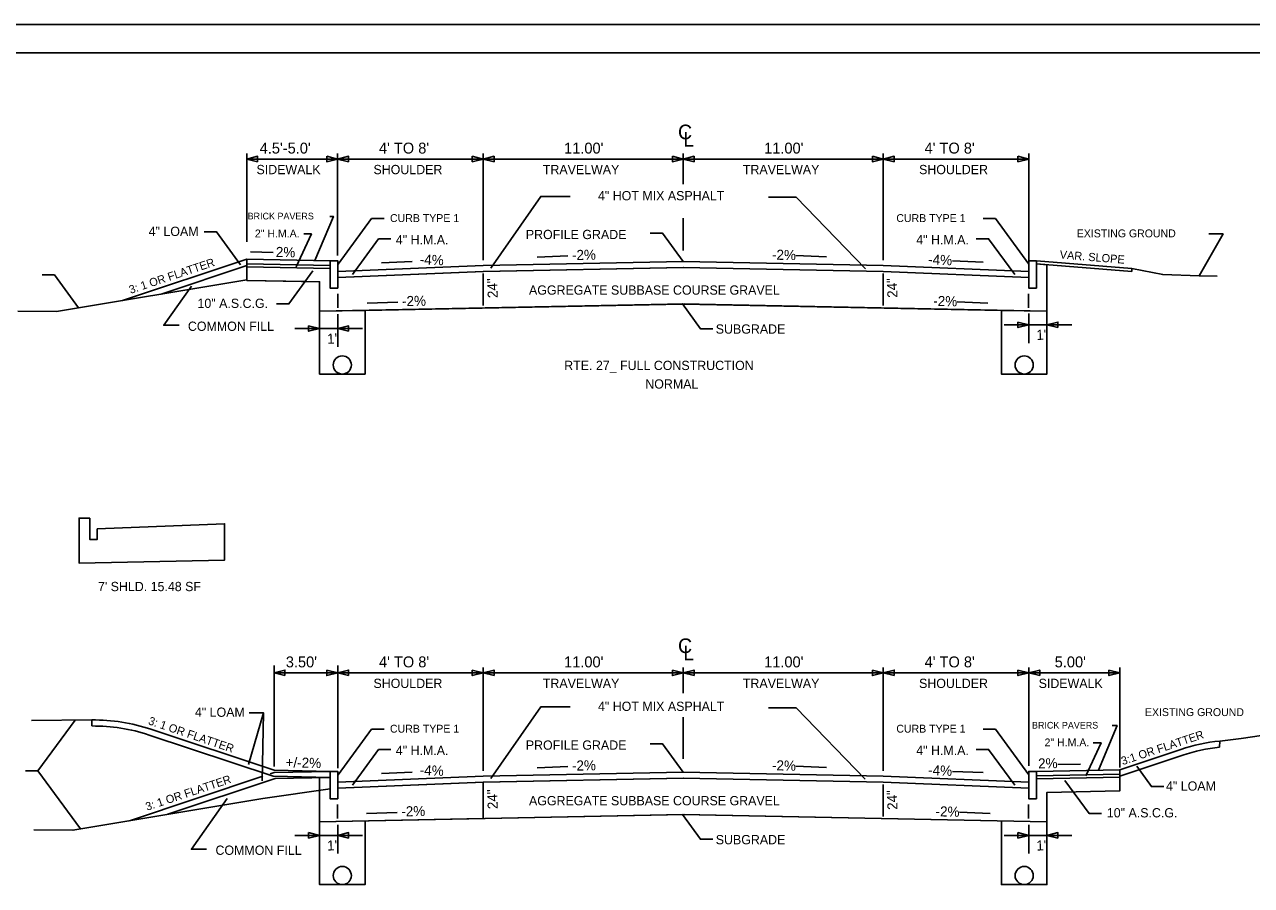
# Model space of a CAD drawing. Extents: x -60 to 130, y -2 to 86.
# Drawn here: x 7.9 to 75.3, y 38.2 to 85.6 of the extents above; entities that cross this region are included whole.
import ezdxf

# ---------------------------------------------------------------- set-up
doc = ezdxf.new("R2010")
doc.units = 0
for name, color, linetype in [('ANNOTATION', 7, 'Continuous'), ('BORDER', 7, 'Continuous'), ('D_Curb_Type1_Lt', 7, 'Continuous'), ('D_Curb_Type1_Rt', 7, 'Continuous'), ('D_Curb_Type_1_Rt', 7, 'Continuous'), ('D_Roadway_Edge_Shoulder', 7, 'Continuous'), ('D_Roadway_Edge_TW', 7, 'Continuous'), ('D_Roadway_FinishedGrade', 7, 'Continuous'), ('D_Roadway_Sidewalks_Paved', 7, 'Continuous'), ('D_Roadway_SubGrade', 7, 'Continuous'), ('DIMENSIONS', 7, 'Continuous'), ('junk gravel', 7, 'Continuous'), ('PATTERNING', 7, 'Continuous'), ('PDRAIN', 7, 'Continuous'), ('PLOT BOUNDARY', 7, 'Continuous'), ('S_Roadway_Centerline', 7, 'Continuous')]:
    doc.layers.add(name, color=color, linetype=linetype)

msp = doc.modelspace()

# ---------------------------------------------------------------- linework, layer by layer
at = {"layer": 'ANNOTATION'}
for p, q in [((21.541, 73.019), (20.296, 73.044)), ((29.184, 72.511), (27.501, 72.444)), ((37.74, 72.819), (36.056, 72.752)), ((50.284, 72.84), (51.968, 72.772)), ((58.908, 72.555), (60.592, 72.487)), ((28.396, 70.285), (26.713, 70.217)), ((59.153, 70.298), (60.836, 70.23)), ((37.74, 44.729), (36.056, 44.662)), ((50.284, 44.75), (51.968, 44.683)), ((64.696, 44.843), (65.941, 44.868)), ((29.184, 44.422), (27.501, 44.354)), ((58.908, 44.465), (60.592, 44.398)), ((28.354, 42.214), (26.67, 42.146)), ((59.28, 42.217), (60.963, 42.15))]:
    msp.add_line(p, q, dxfattribs=at)
for points in [[(37.873, 76.099), (36.254, 76.099), (33.509, 72.144)], [(48.778, 76.051), (50.301, 76.051), (54.117, 72.119)], [(24.652, 75.001), (24.858, 75.001), (23.836, 72.572)], [(27.639, 74.882), (26.959, 74.882), (25.121, 72.365)], [(60.578, 74.882), (61.259, 74.882), (63.096, 72.365)], [(17.75, 74.148), (18.43, 74.148), (19.755, 72.334)], [(23.221, 74.038), (23.648, 74.038), (22.806, 72.217)], [(28.021, 73.766), (27.341, 73.766), (25.904, 71.798)], [(42.274, 74.071), (42.954, 74.071), (44.093, 72.512)], [(60.207, 73.766), (60.887, 73.766), (62.324, 71.798)], [(72.993, 74.034), (73.781, 74.034), (72.454, 71.736)], [(8.838, 71.782), (9.518, 71.782), (10.843, 69.968)], [(21.725, 70.183), (22.405, 70.183), (23.73, 71.998)], [(16.368, 69.007), (15.528, 69.007), (17.05, 71.162)], [(45.719, 68.819), (45.039, 68.819), (44.046, 70.179)], [(37.873, 48.009), (36.254, 48.009), (33.52, 44.07)], [(48.778, 47.961), (50.301, 47.961), (54.105, 44.041)], [(7.931, 44.491), (8.611, 44.491), (10.654, 47.289)], [(20.228, 47.68), (21.017, 47.68), (20.193, 44.838)], [(20.337, 47.68), (21.017, 47.68), (20.944, 43.95)], [(27.639, 46.792), (26.959, 46.792), (25.121, 44.276)], [(60.578, 46.792), (61.259, 46.792), (63.096, 44.276)], [(67.682, 46.982), (67.946, 46.982), (66.931, 44.534)], [(42.274, 45.981), (42.954, 45.981), (44.093, 44.422)], [(66.642, 46.04), (67.069, 46.04), (66.228, 44.219)], [(28.021, 45.677), (27.341, 45.677), (25.904, 43.709)], [(60.207, 45.677), (60.887, 45.677), (62.324, 43.709)], [(70.521, 43.633), (69.841, 43.633), (69.027, 44.747)], [(7.931, 44.491), (8.611, 44.491), (10.94, 41.302)], [(67.087, 42.158), (66.407, 42.158), (65.082, 43.972)], [(17.886, 40.181), (17.046, 40.181), (19.017, 42.973)], [(45.719, 40.729), (45.039, 40.729), (44.046, 42.089)]]:
    msp.add_lwpolyline(points, dxfattribs=at)
at = {"layer": 'BORDER'}
msp.add_line((128, 84), (0, 84), dxfattribs=at)
at = {"layer": 'D_Curb_Type1_Lt'}
for points in [[(24.676, 72.555), (24.676, 71.055), (25.093, 71.055), (25.093, 72.555)], [(24.676, 44.465), (24.676, 42.965), (25.093, 42.965), (25.093, 44.465)]]:
    msp.add_lwpolyline(points, close=True, dxfattribs=at)
at = {"layer": 'D_Curb_Type1_Rt'}
for points in [[(63.509, 72.555), (63.509, 71.055), (63.093, 71.055), (63.093, 72.555)], [(63.509, 44.465), (63.509, 42.965), (63.093, 42.965), (63.093, 44.465)]]:
    msp.add_lwpolyline(points, close=True, dxfattribs=at)
at = {"layer": 'D_Curb_Type_1_Rt'}
msp.add_line((63.509, 42.965), (63.093, 42.965), dxfattribs=at)
at = {"layer": 'D_Roadway_Edge_Shoulder'}
for p, q in [((33.093, 72.292), (25.093, 71.972)), ((55.093, 72.292), (63.093, 71.972)), ((25.093, 71.972), (25.093, 71.638)), ((33.106, 71.959), (25.093, 71.638)), ((55.079, 71.959), (63.093, 71.638)), ((63.093, 71.972), (63.093, 71.638)), ((33.093, 44.202), (25.093, 43.882)), ((25.093, 43.882), (25.093, 43.548)), ((33.106, 43.869), (25.093, 43.548)), ((55.079, 43.869), (63.093, 43.548)), ((55.093, 44.202), (63.093, 43.882)), ((63.093, 43.882), (63.093, 43.548))]:
    msp.add_line(p, q, dxfattribs=at)
at = {"layer": 'D_Roadway_Edge_TW'}
for p, q in [((33.093, 72.292), (44.093, 72.512)), ((44.093, 72.512), (55.093, 72.292)), ((33.099, 71.959), (44.099, 72.179)), ((44.086, 72.179), (55.086, 71.959)), ((33.093, 44.202), (44.093, 44.422)), ((33.099, 43.869), (44.099, 44.089)), ((44.086, 44.089), (55.086, 43.869)), ((44.093, 44.422), (55.093, 44.202))]:
    msp.add_line(p, q, dxfattribs=at)
at = {"layer": 'D_Roadway_FinishedGrade'}
for p, q in [((20.088, 72.647), (13.267, 70.373)), ((20.088, 72.296), (15.382, 70.727)), ((63.509, 72.555), (68.765, 72.129)), ((63.509, 72.388), (68.765, 71.961)), ((68.765, 72.129), (68.765, 71.961)), ((11.574, 47.297), (11.574, 46.964)), ((14.821, 46.784), (21.593, 44.527)), ((14.716, 46.468), (21.535, 44.195)), ((73.587, 45.802), (73.593, 46.137)), ((71.456, 45.677), (68.098, 44.557)), ((71.562, 45.361), (68.098, 44.206)), ((20.967, 44.195), (13.644, 41.754)), ((21.65, 44.072), (15.758, 42.108)), ((21.593, 44.404), (21.371, 44.33))]:
    msp.add_line(p, q, dxfattribs=at)
for centre, radius, start, end in [((11.659, 37.297), 10, 71.56505, 90.48555), ((11.659, 37.297), 9.667, 71.56505, 90.50227), ((74.619, 36.19), 10, 95.88696, 108.43495), ((74.619, 36.19), 9.667, 96.1272, 108.43495)]:
    msp.add_arc(centre, radius, start, end, dxfattribs=at)
at = {"layer": 'D_Roadway_Sidewalks_Paved'}
for p, q in [((20.088, 72.647), (24.676, 72.555)), ((24.676, 72.305), (20.088, 72.397)), ((24.676, 72.138), (20.088, 72.23)), ((63.509, 44.465), (68.098, 44.557)), ((63.509, 44.215), (68.098, 44.307)), ((63.509, 44.048), (68.098, 44.14))]:
    msp.add_line(p, q, dxfattribs=at)
at = {"layer": 'D_Roadway_SubGrade'}
for p, q in [((20.088, 72.647), (20.088, 71.48)), ((64.093, 72.34), (64.093, 69.778)), ((20.088, 71.48), (24.093, 71.4)), ((24.093, 71.4), (24.093, 69.778)), ((24.093, 69.778), (44.139, 70.179)), ((44.046, 70.179), (64.093, 69.778)), ((68.098, 44.557), (68.098, 43.39)), ((21.535, 44.195), (24.669, 44.132)), ((21.593, 44.527), (24.676, 44.465)), ((24.676, 44.465), (21.593, 44.404)), ((24.683, 44.132), (21.65, 44.072)), ((24.093, 44.144), (24.093, 41.688)), ((68.098, 43.39), (64.093, 43.31)), ((64.093, 43.31), (64.093, 41.688)), ((24.093, 41.688), (44.139, 42.089)), ((44.046, 42.089), (64.093, 41.688))]:
    msp.add_line(p, q, dxfattribs=at)
at = {"layer": 'DIMENSIONS'}
for p, q in [((20.088, 73.607), (20.088, 78.455)), ((25.088, 72.855), (25.088, 78.455)), ((33.093, 72.592), (33.093, 78.455)), ((44.093, 76.775), (44.093, 78.455)), ((55.093, 72.592), (55.093, 78.455)), ((63.093, 72.272), (63.093, 78.455)), ((20.088, 78.155), (25.088, 78.155)), ((26.448, 78.155), (25.088, 78.155)), ((25.088, 78.155), (33.093, 78.155)), ((33.093, 78.155), (44.093, 78.155)), ((44.093, 78.155), (55.093, 78.155)), ((55.093, 78.155), (63.093, 78.155)), ((44.093, 73.119), (44.093, 74.905)), ((33.099, 71.859), (33.099, 70.099)), ((55.079, 71.859), (55.079, 70.099)), ((25.093, 70.734), (25.093, 69.959)), ((63.077, 70.734), (63.077, 69.959)), ((25.093, 69.617), (25.093, 67.821)), ((63.093, 69.648), (63.093, 68.032)), ((22.733, 68.825), (24.093, 68.825)), ((24.093, 68.825), (25.093, 68.825)), ((25.093, 68.825), (26.453, 68.825)), ((61.733, 69.035), (63.093, 69.035)), ((63.093, 69.035), (64.093, 69.035)), ((64.093, 69.035), (65.453, 69.035)), ((21.593, 44.727), (21.593, 50.289)), ((25.093, 44.638), (25.093, 50.289)), ((33.093, 44.502), (33.093, 50.189)), ((44.093, 48.766), (44.093, 50.189)), ((55.093, 44.502), (55.093, 50.189)), ((63.098, 44.765), (63.098, 50.189)), ((68.098, 44.857), (68.098, 50.189)), ((68.098, 44.681), (68.098, 50.189)), ((25.093, 49.889), (21.593, 49.889)), ((25.093, 49.889), (33.093, 49.889)), ((33.093, 49.889), (44.093, 49.889)), ((44.093, 49.889), (55.093, 49.889)), ((55.093, 49.889), (63.098, 49.889)), ((63.098, 49.889), (68.098, 49.889)), ((66.738, 49.889), (68.098, 49.889)), ((44.093, 45.15), (44.093, 47.455)), ((33.099, 43.77), (33.099, 42.01)), ((55.079, 43.754), (55.079, 41.994)), ((25.085, 42.644), (25.085, 41.869)), ((63.085, 42.644), (63.085, 41.869)), ((25.093, 41.523), (25.093, 39.942)), ((63.093, 41.523), (63.093, 39.942)), ((22.733, 40.946), (24.093, 40.946)), ((24.093, 40.946), (25.093, 40.946)), ((25.093, 40.946), (26.453, 40.946)), ((61.733, 40.946), (63.093, 40.946)), ((63.093, 40.946), (64.093, 40.946)), ((64.093, 40.946), (65.453, 40.946))]:
    msp.add_line(p, q, dxfattribs=at)
for points in [[(20.688, 78.005), (20.088, 78.155), (20.688, 78.305)], [(24.488, 78.305), (25.088, 78.155), (24.488, 78.005)], [(25.688, 78.005), (25.088, 78.155), (25.688, 78.305)], [(25.688, 78.005), (25.088, 78.155), (25.688, 78.305)], [(32.493, 78.305), (33.093, 78.155), (32.493, 78.005)], [(33.693, 78.005), (33.093, 78.155), (33.693, 78.305)], [(43.493, 78.305), (44.093, 78.155), (43.493, 78.005)], [(44.693, 78.005), (44.093, 78.155), (44.693, 78.305)], [(54.493, 78.305), (55.093, 78.155), (54.493, 78.005)], [(55.693, 78.005), (55.093, 78.155), (55.693, 78.305)], [(62.493, 78.305), (63.093, 78.155), (62.493, 78.005)], [(23.493, 68.975), (24.093, 68.825), (23.493, 68.675)], [(25.693, 68.675), (25.093, 68.825), (25.693, 68.975)], [(62.493, 69.185), (63.093, 69.035), (62.493, 68.885)], [(64.693, 68.885), (64.093, 69.035), (64.693, 69.185)], [(22.193, 49.739), (21.593, 49.889), (22.193, 50.039)], [(24.493, 50.039), (25.093, 49.889), (24.493, 49.739)], [(25.693, 49.739), (25.093, 49.889), (25.693, 50.039)], [(32.493, 50.039), (33.093, 49.889), (32.493, 49.739)], [(33.693, 49.739), (33.093, 49.889), (33.693, 50.039)], [(43.493, 50.039), (44.093, 49.889), (43.493, 49.739)], [(44.693, 49.739), (44.093, 49.889), (44.693, 50.039)], [(54.493, 50.039), (55.093, 49.889), (54.493, 49.739)], [(55.693, 49.739), (55.093, 49.889), (55.693, 50.039)], [(62.498, 50.039), (63.098, 49.889), (62.498, 49.739)], [(63.698, 49.739), (63.098, 49.889), (63.698, 50.039)], [(67.498, 50.039), (68.098, 49.889), (67.498, 49.739)], [(23.493, 41.096), (24.093, 40.946), (23.493, 40.796)], [(25.693, 40.796), (25.093, 40.946), (25.693, 41.096)], [(62.493, 41.096), (63.093, 40.946), (62.493, 40.796)], [(64.693, 40.796), (64.093, 40.946), (64.693, 41.096)]]:
    msp.add_lwpolyline(points, close=True, dxfattribs=at)
at = {"layer": 'junk gravel'}
msp.add_line((10.873, 55.928), (10.873, 58.404), dxfattribs=at)
for points in [[(11.873, 57.808), (11.873, 57.225), (11.456, 57.225), (11.456, 58.392), (11.449, 58.392), (10.873, 58.404), (10.873, 55.928), (18.873, 56.088), (18.873, 58.088), (11.873, 57.808)], [(25.093, 43.548), (25.093, 42.965), (24.676, 42.965), (24.676, 44.132), (24.093, 44.121), (24.093, 44.121), (24.093, 41.688), (33.099, 41.868), (33.099, 43.869), (25.093, 43.548)]]:
    msp.add_lwpolyline(points, dxfattribs=at)
at = {"layer": 'PATTERNING'}
for points in [[(64.093, 72.34), (63.509, 72.388), (63.509, 72.388), (63.509, 71.055), (63.093, 71.055), (63.093, 71.638), (55.086, 71.959), (55.083, 71.959), (55.079, 71.959), (44.093, 72.179), (33.106, 71.959), (33.103, 71.959), (33.099, 71.959), (25.093, 71.638), (25.093, 71.055), (24.676, 71.055), (24.676, 72.138), (24.676, 72.138), (20.088, 72.23), (20.088, 71.48), (24.093, 71.4), (24.093, 69.778), (44.093, 70.178), (64.093, 69.778)], [(23.304, 71.416), (24.093, 71.4), (24.093, 69.778), (26.593, 69.828), (44.047, 70.177), (44.046, 70.179), (44.093, 70.178), (61.593, 69.828), (64.093, 69.778), (64.093, 72.34), (63.509, 72.388), (63.509, 71.055), (63.093, 71.055), (63.093, 71.638), (63.09, 71.638), (55.086, 71.959), (55.083, 71.959), (55.079, 71.959), (44.093, 72.179), (33.106, 71.959), (33.103, 71.959), (33.099, 71.959), (25.095, 71.638), (25.093, 71.638), (25.093, 71.055), (24.676, 71.055), (24.676, 72.138), (20.088, 72.23), (20.088, 72.314), (20.088, 71.514), (20.088, 71.48)], [(63.509, 44.048), (63.509, 42.965), (63.093, 42.965), (63.093, 43.548), (55.086, 43.869), (55.083, 43.869), (55.079, 43.869), (44.093, 44.089), (33.106, 43.869), (33.103, 43.869), (33.099, 43.869), (25.093, 43.548), (25.093, 42.965), (24.676, 42.965), (24.676, 44.132), (24.093, 44.121), (24.093, 41.688), (44.093, 42.088), (64.093, 41.688), (64.093, 43.31), (68.098, 43.39), (68.098, 44.14), (63.509, 44.048)], [(63.509, 43.715), (63.509, 42.965), (63.093, 42.965), (63.093, 43.548), (55.086, 43.869), (55.083, 43.869), (55.079, 43.869), (44.093, 44.089), (33.106, 43.869), (33.103, 43.869), (33.099, 43.869), (25.093, 43.548), (25.093, 42.965), (24.676, 42.965), (24.676, 44.132), (24.093, 44.121), (24.093, 41.688), (44.093, 42.088), (64.093, 41.688), (64.093, 43.31), (68.098, 43.39), (68.098, 44.14), (63.509, 44.048)]]:
    msp.add_lwpolyline(points, close=True, dxfattribs=at)
at = {"layer": 'PDRAIN'}
for points in [[(24.093, 69.778), (24.093, 66.327), (26.593, 66.327), (26.593, 69.828)], [(61.593, 69.828), (61.593, 66.327), (64.093, 66.327), (64.093, 69.778)], [(24.093, 41.688), (24.093, 38.237), (26.593, 38.237), (26.593, 41.738)], [(61.593, 41.738), (61.593, 38.237), (64.093, 38.237), (64.093, 41.688)]]:
    msp.add_lwpolyline(points, dxfattribs=at)
for centre in [(25.343, 66.827), (62.843, 66.827), (25.343, 38.737), (62.843, 38.737)]:
    msp.add_circle(centre, 0.5, dxfattribs=at)
at = {"layer": 'PLOT BOUNDARY'}
msp.add_lwpolyline([(-6.475, -2.447), (129.525, -2.447), (129.525, 85.553), (-6.475, 85.553)], close=True, dxfattribs=at)
at = {"layer": 'S_Roadway_Centerline'}
msp.add_line((20.984, 42.982), (24.676, 43.511), dxfattribs=at)
for points in [[(68.765, 72.129), (70.457, 71.8), (72.454, 71.736), (73.454, 71.705)], [(20.088, 71.514), (9.636, 69.766), (7.494, 69.789)], [(11.574, 47.297), (8.261, 47.269)], [(73.593, 46.137), (74.772, 46.277), (76.387, 46.507), (77.428, 46.724), (79.821, 47.173)], [(20.984, 42.982), (10.533, 41.233), (8.39, 41.257)]]:
    msp.add_lwpolyline(points, dxfattribs=at)

# ---------------------------------------------------------------- texts
at = {"layer": 'ANNOTATION'}
for s, height, p in [('C', 0.805, (43.804, 79.241)), ('L', 0.805, (44.093, 78.838)), ("4.5'-5.0'", 0.6, (20.803, 78.455)), ("4' TO 8'", 0.6, (27.36, 78.455)), ("11.00'", 0.6, (37.541, 78.455)), ("11.00'", 0.6, (48.541, 78.455)), ("4' TO 8'", 0.6, (57.362, 78.455)), ('SIDEWALK', 0.51, (20.626, 77.32)), ('SHOULDER', 0.51, (27.058, 77.32)), ('TRAVELWAY', 0.51, (36.372, 77.32)), ('TRAVELWAY', 0.51, (47.372, 77.32)), ('SHOULDER', 0.51, (57.06, 77.32)), ('4" HOT MIX ASPHALT', 0.51, (39.405, 75.882)), ('BRICK PAVERS', 0.36847, (20.137, 74.83)), ('CURB TYPE 1', 0.4335, (27.968, 74.688)), ('CURB TYPE 1', 0.4335, (55.811, 74.688)), ('4" LOAM', 0.51, (14.698, 73.919)), ('2" H.M.A.', 0.4335, (20.537, 73.842)), ('PROFILE GRADE', 0.51, (35.436, 73.748)), ('EXISTING GROUND', 0.4335, (65.733, 73.846)), ('4" H.M.A.', 0.51, (28.288, 73.458)), ('4" H.M.A.', 0.51, (56.906, 73.458)), ('AGGREGATE SUBBASE COURSE GRAVEL', 0.51, (35.609, 70.69)), ('10" A.S.C.G.', 0.51, (17.382, 69.961)), ('COMMON FILL', 0.51, (16.855, 68.701)), ('SUBGRADE', 0.51, (45.88, 68.547)), ('RTE. 27_ FULL CONSTRUCTION', 0.51, (37.548, 66.545)), ('NORMAL', 0.51, (42.006, 65.525)), ('C', 0.805, (43.804, 50.975)), ('L', 0.805, (44.093, 50.573)), ("4' TO 8'", 0.6, (27.362, 50.189)), ("11.00'", 0.6, (37.541, 50.189)), ("11.00'", 0.6, (48.541, 50.189)), ("4' TO 8'", 0.6, (57.365, 50.189)), ("5.00'", 0.6, (64.519, 50.189)), ('SHOULDER', 0.51, (27.058, 49.054)), ('TRAVELWAY', 0.51, (36.372, 49.054)), ('TRAVELWAY', 0.51, (47.372, 49.054)), ('SHOULDER', 0.51, (57.06, 49.054)), ('SIDEWALK', 0.51, (63.636, 49.054)), ('4" LOAM', 0.51, (17.24, 47.468)), ('4" HOT MIX ASPHALT', 0.51, (39.405, 47.793)), ('EXISTING GROUND', 0.4335, (69.482, 47.509)), ('CURB TYPE 1', 0.4335, (27.968, 46.599)), ('CURB TYPE 1', 0.4335, (55.811, 46.599)), ('BRICK PAVERS', 0.36847, (63.27, 46.821)), ('4" H.M.A.', 0.51, (28.288, 45.368)), ('PROFILE GRADE', 0.51, (35.436, 45.659)), ('4" H.M.A.', 0.51, (56.906, 45.368)), ('2" H.M.A.', 0.4335, (63.959, 45.844)), ('4" LOAM', 0.51, (70.64, 43.405)), ('AGGREGATE SUBBASE COURSE GRAVEL', 0.51, (35.609, 42.6)), ('10" A.S.C.G.', 0.51, (67.387, 41.935)), ('SUBGRADE', 0.51, (45.88, 40.457)), ('COMMON FILL', 0.51, (18.372, 39.876))]:
    msp.add_text(s, height=height, dxfattribs=at).set_placement(p)
for s, height, rotation, p in [('2%', 0.5541, 358.85424, (21.685, 72.767)), ('-4%', 0.5541, 357.70939, (29.595, 72.358)), ('-2%', 0.5541, 1.14576, (37.979, 72.592)), ('-2%', 0.5541, 358.85424, (48.968, 72.617)), ('-4%', 0.5541, 357.70939, (57.551, 72.358)), ('VAR. SLOPE', 0.45, 355.35424, (64.782, 72.683)), ('3: 1 OR FLATTER', 0.45, 18.43495, (13.704, 70.734)), ('24"', 0.5541, 92.29061, (33.896, 70.515)), ('24"', 0.5541, 92.29061, (55.876, 70.53)), ('-2%', 0.5541, 1.14576, (28.635, 70.058)), ('-2%', 0.5541, 358.85424, (57.836, 70.075)), ("1'", 0.5541, 2.29061, (24.519, 67.986)), ("1'", 0.5541, 2.29061, (63.519, 68.197)), ('3: 1 OR FLATTER', 0.45, 341.24968, (14.641, 47.068)), ('3:1 OR FLATTER', 0.45, 18.43495, (68.258, 44.807)), ('+/-2%', 0.5541, 358.85424, (22.222, 44.688)), ('-4%', 0.5541, 357.70939, (29.595, 44.269)), ('-2%', 0.5541, 1.14576, (37.979, 44.503)), ('-2%', 0.5541, 358.85424, (48.968, 44.527)), ('-4%', 0.5541, 357.70939, (57.551, 44.269)), ('2%', 0.5541, 1.14576, (63.61, 44.624)), ('3: 1 OR FLATTER', 0.45, 18.43495, (14.611, 42.297)), ('24"', 0.5541, 92.29061, (33.896, 42.402)), ('24"', 0.5541, 92.29061, (55.876, 42.363)), ('-2%', 0.5541, 1.14576, (28.593, 41.987)), ('-2%', 0.5541, 358.85424, (57.963, 41.994)), ("1'", 0.5541, 2.29061, (24.519, 40.107)), ("1'", 0.5541, 2.29061, (63.519, 40.107))]:
    msp.add_text(s, height=height, rotation=rotation, dxfattribs=at).set_placement(p)
at = {"layer": 'DIMENSIONS'}
msp.add_text("3.50'", height=0.6, dxfattribs=at).set_placement((22.238, 50.189))
at = {"layer": 'junk gravel'}
msp.add_text("7' SHLD. 15.48 SF", height=0.51, dxfattribs=at).set_placement((11.909, 54.382))

doc.saveas('drawing.dxf')
